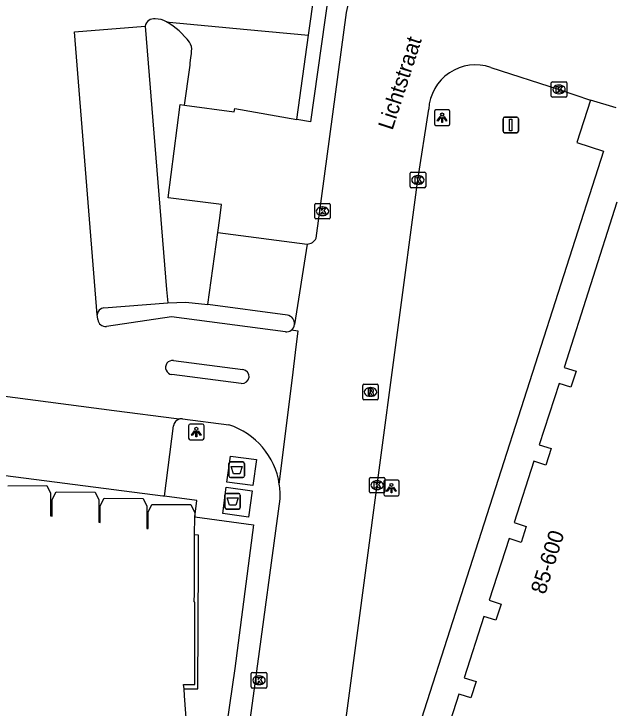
# Model space of a CAD drawing. Extents: x 160676 to 161153, y 383244 to 383713.
# Drawn here: x 160773.69 to 160812.07, y 383306.9 to 383351.55 of the extents above; entities that cross this region are included whole.
import ezdxf

# ---------------------------------------------------------------- set-up
doc = ezdxf.new("R2010")
doc.units = 0
for name, color, linetype in [('IMGEO_Afsluitpaal', 7, 'Continuous'), ('IMGEO_Afval_apart_plaats', 7, 'Continuous'), ('IMGEO_Kolk', 7, 'Continuous'), ('IMGEO_Lichtpunt', 7, 'Continuous'), ('IMGEO_Muur', 7, 'Continuous'), ('IMGEO_Openbare_ruimte_label', 7, 'Continuous'), ('IMGEO_Pand', 7, 'Continuous'), ('IMGEO_Pand_nummerreeks', 7, 'Continuous'), ('IMGEO_Parkeervlak_open', 7, 'Continuous'), ('IMGEO_Rijbaan_lokaal_open', 7, 'Continuous'), ('IMGEO_Rioolput', 7, 'Continuous'), ('IMGEO_Verkeerseiland_open', 7, 'Continuous'), ('IMGEO_Voetpad_gesloten', 7, 'Continuous'), ('IMGEO_Voetpad_open', 7, 'Continuous')]:
    doc.layers.add(name, color=color, linetype=linetype)

msp = doc.modelspace()

# ---------------------------------------------------------------- linework, layer by layer
at = {"layer": 'IMGEO_Afsluitpaal'}
for p, q in [((160805.175, 383344.01), (160805.175, 383344.81)), ((160805.175, 383344.81), (160805.175, 383344.01)), ((160805.275, 383344.91), (160806.065, 383344.91)), ((160806.065, 383344.91), (160805.275, 383344.91)), ((160806.165, 383344.81), (160806.165, 383344.01)), ((160806.165, 383344.01), (160806.165, 383344.81)), ((160806.065, 383343.91), (160805.275, 383343.91)), ((160805.275, 383343.91), (160806.065, 383343.91))]:
    msp.add_line(p, q, dxfattribs=at)
msp.add_lwpolyline([(160805.595, 383344.785), (160805.745, 383344.785), (160805.745, 383344.035), (160805.595, 383344.035), (160805.595, 383344.785)], dxfattribs=at)
for centre, start, end in [((160805.275, 383344.81), 90, 180), ((160805.275, 383344.81), 90, 180), ((160806.065, 383344.81), 0, 90), ((160806.065, 383344.81), 360, 90), ((160805.275, 383344.01), 180, 270), ((160805.275, 383344.01), 180, 270), ((160806.065, 383344.01), 270, 0), ((160806.065, 383344.01), 270, 0)]:
    msp.add_arc(centre, 0.1, start, end, dxfattribs=at)
at = {"layer": 'IMGEO_Afval_apart_plaats'}
for p, q in [((160787.535, 383321.83), (160787.535, 383322.63)), ((160787.535, 383322.63), (160787.535, 383321.83)), ((160787.635, 383322.73), (160788.425, 383322.73)), ((160788.425, 383322.73), (160787.635, 383322.73)), ((160788.525, 383322.63), (160788.525, 383321.83)), ((160788.525, 383321.83), (160788.525, 383322.63)), ((160788.425, 383321.73), (160787.635, 383321.73)), ((160787.635, 383321.73), (160788.425, 383321.73)), ((160787.275, 383319.8), (160787.275, 383320.6)), ((160787.275, 383320.6), (160787.275, 383319.8)), ((160787.375, 383320.7), (160788.165, 383320.7)), ((160788.165, 383320.7), (160787.375, 383320.7)), ((160788.265, 383320.6), (160788.265, 383319.8)), ((160788.265, 383319.8), (160788.265, 383320.6)), ((160788.165, 383319.7), (160787.375, 383319.7)), ((160787.375, 383319.7), (160788.165, 383319.7))]:
    msp.add_line(p, q, dxfattribs=at)
for points in [[(160787.678, 383322.444), (160788.382, 383322.444), (160788.233, 383321.974), (160787.827, 383321.974), (160787.678, 383322.444)], [(160787.418, 383320.414), (160788.122, 383320.414), (160787.973, 383319.944), (160787.567, 383319.944), (160787.418, 383320.414)]]:
    msp.add_lwpolyline(points, dxfattribs=at)
for centre, start, end in [((160787.635, 383322.63), 90, 180), ((160787.635, 383322.63), 90, 180), ((160788.425, 383322.63), 0, 90), ((160788.425, 383322.63), 360, 90), ((160787.635, 383321.83), 180, 270), ((160787.635, 383321.83), 180, 270), ((160788.425, 383321.83), 270, 0), ((160788.425, 383321.83), 270, 0), ((160787.375, 383320.6), 90, 180), ((160787.375, 383320.6), 90, 180), ((160788.165, 383320.6), 0, 90), ((160788.165, 383320.6), 360, 90), ((160787.375, 383319.8), 180, 270), ((160787.375, 383319.8), 180, 270), ((160788.165, 383319.8), 270, 0), ((160788.165, 383319.8), 270, 0)]:
    msp.add_arc(centre, 0.1, start, end, dxfattribs=at)
at = {"layer": 'IMGEO_Kolk'}
for p, q in [((160808.356, 383347.194), (160809.208, 383347.194)), ((160808.281, 383346.268), (160808.281, 383347.12)), ((160808.769, 383346.974), (160808.794, 383346.974)), ((160809.282, 383347.12), (160809.282, 383346.268)), ((160808.792, 383346.414), (160808.767, 383346.414)), ((160809.208, 383346.194), (160808.356, 383346.194)), ((160799.269, 383341.373), (160800.121, 383341.373)), ((160799.194, 383340.447), (160799.194, 383341.299)), ((160799.682, 383341.153), (160799.707, 383341.153)), ((160800.195, 383341.299), (160800.195, 383340.447)), ((160799.705, 383340.593), (160799.68, 383340.593)), ((160800.121, 383340.373), (160799.269, 383340.373)), ((160793.054, 383338.434), (160793.054, 383339.286)), ((160793.129, 383339.36), (160793.981, 383339.36)), ((160793.542, 383339.14), (160793.567, 383339.14)), ((160794.055, 383339.286), (160794.055, 383338.434)), ((160793.981, 383338.36), (160793.129, 383338.36)), ((160793.565, 383338.58), (160793.54, 383338.58)), ((160796.645, 383321.737), (160797.497, 383321.737)), ((160796.57, 383320.811), (160796.57, 383321.663)), ((160797.058, 383321.517), (160797.083, 383321.517)), ((160797.571, 383321.663), (160797.571, 383320.811)), ((160797.081, 383320.957), (160797.056, 383320.957)), ((160797.497, 383320.737), (160796.645, 383320.737)), ((160789.047, 383309.187), (160789.899, 383309.187)), ((160788.972, 383308.261), (160788.972, 383309.113)), ((160789.46, 383308.967), (160789.485, 383308.967)), ((160789.973, 383309.113), (160789.973, 383308.261)), ((160789.483, 383308.407), (160789.458, 383308.407)), ((160789.899, 383308.187), (160789.047, 383308.187))]:
    msp.add_line(p, q, dxfattribs=at)
for points in [[(160808.356, 383347.194), (160809.208, 383347.194)], [(160808.281, 383346.268), (160808.281, 383347.12)], [(160808.602, 383346.894), (160808.725, 383346.894), (160808.725, 383346.743), (160808.855, 383346.894), (160809.019, 383346.894), (160808.873, 383346.743), (160809.026, 383346.494), (160808.874, 383346.494), (160808.789, 383346.658), (160808.725, 383346.591), (160808.725, 383346.494), (160808.602, 383346.494), (160808.602, 383346.894)], [(160809.282, 383347.12), (160809.282, 383346.268)], [(160809.208, 383346.194), (160808.356, 383346.194)], [(160799.269, 383341.373), (160800.121, 383341.373)], [(160799.194, 383340.447), (160799.194, 383341.299)], [(160799.515, 383341.073), (160799.638, 383341.073), (160799.638, 383340.922), (160799.768, 383341.073), (160799.932, 383341.073), (160799.786, 383340.922), (160799.939, 383340.673), (160799.787, 383340.673), (160799.702, 383340.837), (160799.638, 383340.77), (160799.638, 383340.673), (160799.515, 383340.673), (160799.515, 383341.073)], [(160800.195, 383341.299), (160800.195, 383340.447)], [(160800.121, 383340.373), (160799.269, 383340.373)], [(160793.054, 383338.434), (160793.054, 383339.286)], [(160793.129, 383339.36), (160793.981, 383339.36)], [(160794.055, 383339.286), (160794.055, 383338.434)], [(160793.375, 383339.06), (160793.498, 383339.06), (160793.498, 383338.909), (160793.628, 383339.06), (160793.792, 383339.06), (160793.646, 383338.909), (160793.799, 383338.66), (160793.647, 383338.66), (160793.562, 383338.824), (160793.498, 383338.757), (160793.498, 383338.66), (160793.375, 383338.66), (160793.375, 383339.06)], [(160793.981, 383338.36), (160793.129, 383338.36)], [(160796.645, 383321.737), (160797.497, 383321.737)], [(160796.57, 383320.811), (160796.57, 383321.663)], [(160796.891, 383321.437), (160797.014, 383321.437), (160797.014, 383321.286), (160797.144, 383321.437), (160797.308, 383321.437), (160797.162, 383321.286), (160797.315, 383321.037), (160797.163, 383321.037), (160797.078, 383321.201), (160797.014, 383321.134), (160797.014, 383321.037), (160796.891, 383321.037), (160796.891, 383321.437)], [(160797.571, 383321.663), (160797.571, 383320.811)], [(160797.497, 383320.737), (160796.645, 383320.737)], [(160789.047, 383309.187), (160789.899, 383309.187)], [(160788.972, 383308.261), (160788.972, 383309.113)], [(160789.293, 383308.887), (160789.416, 383308.887), (160789.416, 383308.736), (160789.546, 383308.887), (160789.71, 383308.887), (160789.564, 383308.736), (160789.717, 383308.487), (160789.565, 383308.487), (160789.48, 383308.651), (160789.416, 383308.584), (160789.416, 383308.487), (160789.293, 383308.487), (160789.293, 383308.887)], [(160789.973, 383309.113), (160789.973, 383308.261)], [(160789.899, 383308.187), (160789.047, 383308.187)]]:
    msp.add_lwpolyline(points, dxfattribs=at)
for centre, start, end in [((160808.358, 383347.118), 91.552, 178.448), ((160808.358, 383347.118), 91.552, 178.448), ((160809.206, 383347.118), 1.552, 88.448), ((160809.206, 383347.118), 1.552, 88.448), ((160808.358, 383346.27), 181.552, 268.448), ((160808.358, 383346.27), 181.552, 268.448), ((160809.206, 383346.27), 271.552, 358.448), ((160809.206, 383346.27), 271.552, 358.448), ((160799.271, 383341.297), 91.552, 178.448), ((160799.271, 383341.297), 91.552, 178.448), ((160800.119, 383341.297), 1.552, 88.448), ((160800.119, 383341.297), 1.552, 88.448), ((160799.271, 383340.449), 181.552, 268.448), ((160799.271, 383340.449), 181.552, 268.448), ((160800.119, 383340.449), 271.552, 358.448), ((160800.119, 383340.449), 271.552, 358.448), ((160793.131, 383339.284), 91.552, 178.448), ((160793.131, 383339.284), 91.552, 178.448), ((160793.979, 383339.284), 1.552, 88.448), ((160793.979, 383339.284), 1.552, 88.448), ((160793.131, 383338.436), 181.552, 268.448), ((160793.131, 383338.436), 181.552, 268.448), ((160793.979, 383338.436), 271.552, 358.448), ((160793.979, 383338.436), 271.552, 358.448), ((160796.647, 383321.661), 91.552, 178.448), ((160796.647, 383321.661), 91.552, 178.448), ((160797.495, 383321.661), 1.552, 88.448), ((160797.495, 383321.661), 1.552, 88.448), ((160796.647, 383320.813), 181.552, 268.448), ((160796.647, 383320.813), 181.552, 268.448), ((160797.495, 383320.813), 271.552, 358.448), ((160797.495, 383320.813), 271.552, 358.448), ((160789.049, 383309.111), 91.552, 178.448), ((160789.049, 383309.111), 91.552, 178.448), ((160789.897, 383309.111), 1.552, 88.448), ((160789.897, 383309.111), 1.552, 88.448), ((160789.049, 383308.263), 181.552, 268.448), ((160789.049, 383308.263), 181.552, 268.448), ((160789.897, 383308.263), 271.552, 358.448), ((160789.897, 383308.263), 271.552, 358.448)]:
    msp.add_arc(centre, 0.0765, start, end, dxfattribs=at)
for centre, major_axis, ratio, start_param, end_param in [((160808.768, 383346.694), (-0.387, 0.002), 0.722429, 4.712389, 7.853982), ((160808.793, 383346.694), (-0.39, 0.002), 0.717154, 1.570796, 4.712389), ((160799.681, 383340.873), (-0.387, 0.002), 0.722429, 4.712389, 7.853982), ((160799.706, 383340.873), (-0.39, 0.002), 0.717154, 1.570796, 4.712389), ((160793.541, 383338.86), (-0.387, 0.002), 0.722429, 4.712389, 7.853982), ((160793.566, 383338.86), (-0.39, 0.002), 0.717154, 1.570796, 4.712389), ((160797.057, 383321.237), (-0.387, 0.002), 0.722429, 4.712389, 7.853982), ((160797.082, 383321.237), (-0.39, 0.002), 0.717154, 1.570796, 4.712389), ((160789.459, 383308.687), (-0.387, 0.002), 0.722429, 4.712389, 7.853982), ((160789.484, 383308.687), (-0.39, 0.002), 0.717154, 1.570796, 4.712389)]:
    msp.add_ellipse(centre, major_axis=major_axis, ratio=ratio, start_param=start_param, end_param=end_param, dxfattribs=at)
at = {"layer": 'IMGEO_Lichtpunt'}
for p, q in [((160801.658, 383345.378), (160800.85, 383345.378)), ((160801.658, 383345.378), (160800.85, 383345.378)), ((160800.756, 383345.283), (160800.756, 383344.476)), ((160800.756, 383345.283), (160800.756, 383344.476)), ((160801.752, 383344.476), (160801.752, 383345.283)), ((160801.752, 383344.476), (160801.752, 383345.283)), ((160800.85, 383344.382), (160801.658, 383344.382)), ((160800.85, 383344.382), (160801.658, 383344.382)), ((160784.937, 383325.063), (160784.937, 383324.256)), ((160784.937, 383325.063), (160784.937, 383324.256)), ((160785.839, 383325.158), (160785.031, 383325.158)), ((160785.839, 383325.158), (160785.031, 383325.158)), ((160785.933, 383324.256), (160785.933, 383325.063)), ((160785.933, 383324.256), (160785.933, 383325.063)), ((160785.031, 383324.162), (160785.839, 383324.162)), ((160785.031, 383324.162), (160785.839, 383324.162)), ((160797.493, 383321.456), (160797.493, 383320.649)), ((160797.493, 383321.456), (160797.493, 383320.649)), ((160798.395, 383321.551), (160797.587, 383321.551)), ((160798.395, 383321.551), (160797.587, 383321.551)), ((160798.489, 383320.649), (160798.489, 383321.456)), ((160798.489, 383320.649), (160798.489, 383321.456)), ((160797.587, 383320.555), (160798.395, 383320.555)), ((160797.587, 383320.555), (160798.395, 383320.555))]:
    msp.add_line(p, q, dxfattribs=at)
for points in [[(160801.13, 383344.947), (160801.169, 383344.919), (160800.981, 383344.657), (160800.943, 383344.684), (160801.13, 383344.947)], [(160801.342, 383344.919), (160801.38, 383344.946), (160801.567, 383344.684), (160801.528, 383344.656), (160801.342, 383344.919)], [(160801.232, 383344.899), (160801.279, 383344.899), (160801.279, 383344.577), (160801.232, 383344.577), (160801.232, 383344.899)], [(160785.311, 383324.727), (160785.35, 383324.699), (160785.162, 383324.437), (160785.124, 383324.464), (160785.311, 383324.727)], [(160785.413, 383324.679), (160785.46, 383324.679), (160785.46, 383324.357), (160785.413, 383324.357), (160785.413, 383324.679)], [(160785.523, 383324.699), (160785.561, 383324.726), (160785.748, 383324.464), (160785.709, 383324.436), (160785.523, 383324.699)], [(160797.867, 383321.12), (160797.906, 383321.092), (160797.718, 383320.83), (160797.68, 383320.857), (160797.867, 383321.12)], [(160797.969, 383321.072), (160798.016, 383321.072), (160798.016, 383320.75), (160797.969, 383320.75), (160797.969, 383321.072)], [(160798.079, 383321.092), (160798.117, 383321.119), (160798.304, 383320.857), (160798.265, 383320.829), (160798.079, 383321.092)]]:
    msp.add_lwpolyline(points, dxfattribs=at)
for centre in [(160801.255, 383345.081), (160785.436, 383324.861), (160797.992, 383321.254)]:
    msp.add_circle(centre, 0.0994, dxfattribs=at)
for centre, start, end in [((160800.85, 383345.283), 90, 180), ((160800.85, 383345.283), 90, 180), ((160801.658, 383345.283), 0, 90), ((160801.658, 383345.283), 0, 90), ((160800.85, 383344.476), 180, 270), ((160800.85, 383344.476), 180, 270), ((160801.658, 383344.476), 270, 0), ((160801.658, 383344.476), 270, 360), ((160785.031, 383325.063), 90, 180), ((160785.031, 383325.063), 90, 180), ((160785.839, 383325.063), 0, 90), ((160785.839, 383325.063), 0, 90), ((160785.031, 383324.256), 180, 270), ((160785.031, 383324.256), 180, 270), ((160785.839, 383324.256), 270, 0), ((160785.839, 383324.256), 270, 360), ((160797.587, 383321.456), 90, 180), ((160797.587, 383321.456), 90, 180), ((160798.395, 383321.456), 0, 90), ((160798.395, 383321.456), 0, 90), ((160797.587, 383320.649), 180, 270), ((160797.587, 383320.649), 180, 270), ((160798.395, 383320.649), 270, 0), ((160798.395, 383320.649), 270, 360)]:
    msp.add_arc(centre, 0.0946, start, end, dxfattribs=at)
at = {"layer": 'IMGEO_Muur'}
msp.add_lwpolyline([(160784.642, 383308.13), (160785.536, 383308.126), (160785.57, 383316.389), (160785.576, 383317.889), (160785.577, 383318.015), (160785.325, 383318.048)], dxfattribs=at)
at = {"layer": 'IMGEO_Pand'}
for points in [[(160812.507, 383339.449), (160809.099, 383328.814), (160809.87, 383328.567), (160809.547, 383327.538), (160808.776, 383327.786), (160807.505, 383323.835), (160808.276, 383323.587), (160807.93, 383322.528), (160807.159, 383322.776), (160805.888, 383318.832), (160806.658, 383318.584), (160806.332, 383317.554), (160805.562, 383317.803), (160804.281, 383313.834), (160805.052, 383313.585), (160804.718, 383312.546), (160803.946, 383312.793), (160802.682, 383308.844), (160803.453, 383308.597), (160803.105, 383307.552), (160802.409, 383307.77), (160802.332, 383307.794), (160796.79, 383290.554)], [(160773.307, 383321.203), (160775.806, 383321.216), (160776.054, 383320.717), (160776.055, 383319.264), (160776.161, 383319.25), (160776.161, 383320.31), (160776.415, 383320.808), (160778.923, 383320.79), (160779.166, 383320.286), (160779.166, 383318.856), (160779.243, 383318.846), (160779.243, 383319.899), (160779.496, 383320.398), (160782.011, 383320.385), (160782.256, 383319.881), (160782.257, 383318.451), (160782.326, 383318.441), (160782.326, 383319.498), (160782.577, 383319.997), (160785.09, 383319.987), (160785.332, 383319.46), (160785.331, 383319.191)], [(160785.325, 383318.048), (160785.331, 383319.191)], [(160784.642, 383308.13), (160784.62, 383308.419), (160785.333, 383308.411), (160785.346, 383313.718), (160785.304, 383313.73), (160785.307, 383314.278), (160785.325, 383318.048)], [(160784.931, 383304.271), (160784.675, 383307.69), (160784.642, 383308.13)]]:
    msp.add_lwpolyline(points, dxfattribs=at)
at = {"layer": 'IMGEO_Parkeervlak_open'}
for points in [[(160782.144, 383350.764), (160783.513, 383333.834), (160783.609, 383332.967)], [(160791.912, 383344.759), (160792.66, 383350.191)], [(160784.68, 383345.68), (160785.01, 383348.104), (160785.029, 383348.254), (160785.048, 383348.404), (160785.067, 383348.553), (160785.09, 383348.743), (160785.103, 383348.852), (160785.119, 383349.001), (160785.13, 383349.166)], [(160786.168, 383332.849), (160786.829, 383337.493)], [(160779.492, 383332.635), (160783.609, 383332.967)], [(160791.296, 383332.168), (160786.168, 383332.849)], [(160783.387, 383320.523), (160783.274, 383320.538), (160773.83, 383321.747), (160754.886, 383324.173)]]:
    msp.add_lwpolyline(points, dxfattribs=at)
for centre, radius, start, end in [((160780.823, 383346.537), 5.254, 37.3771, 59.0622), ((160784.326, 383349.272), 0.811, 352.4855, 34.0412), ((160779.521, 383332.174), 0.462, 93.5519, 177.7562), ((160791.212, 383331.636), 0.539, 353.5978, 81.0043)]:
    msp.add_arc(centre, radius, start, end, dxfattribs=at)
at = {"layer": 'IMGEO_Rijbaan_lokaal_open'}
for points in [[(160793.154, 383337.121), (160795.11, 383351.65), (160795.304, 383352.64), (160797.946, 383359.432)], [(160792.66, 383350.191), (160793.037, 383352.925), (160793.742, 383354.783)], [(160779.059, 383332.192), (160777.595, 383350.398), (160782.144, 383350.764)], [(160783.524, 383351.043), (160783.678, 383351.029), (160788.706, 383350.56), (160792.66, 383350.191)], [(160804.384, 383348.108), (160808.782, 383346.694), (160810.812, 383346.001)], [(160812.457, 383345.502), (160810.812, 383346.001)], [(160793.115, 383291.71), (160794.447, 383301.572), (160797.071, 383321.237), (160799.695, 383340.873), (160800.391, 383345.424)], [(160792.564, 383336.747), (160791.747, 383331.576)], [(160779.088, 383331.889), (160779.068, 383332.083), (160779.059, 383332.192)], [(160791.175, 383331.099), (160783.842, 383332.057), (160779.649, 383331.453)], [(160790.776, 383321.303), (160791.621, 383328.132), (160791.869, 383330.134), (160791.995, 383331.154), (160791.53, 383331.202)], [(160784.323, 383325.486), (160784.152, 383325.508), (160780.14, 383326.029), (160771.64, 383327.131), (160768.888, 383327.489), (160757.053, 383329.024), (160755.161, 383329.27)], [(160783.962, 383329.258), (160788.435, 383328.678)], [(160788.327, 383327.783), (160783.854, 383328.354)], [(160784.542, 383325.513), (160787.527, 383325.118)], [(160787.712, 383297.432), (160789.229, 383308.479), (160790.827, 383320.367)]]:
    msp.add_lwpolyline(points, dxfattribs=at)
for centre, radius, start, end in [((160782.705, 383350.673), 0.568, 81.4504, 170.8259), ((160782.787, 383349.723), 1.512, 60.8148, 89.9054), ((160803.398, 383345.263), 3.011, 70.8811, 176.9351), ((160792.52, 383337.469), 0.724, 273.506, 331.2351), ((160779.604, 383331.974), 0.523, 189.3186, 274.9739), ((160791.238, 383331.622), 0.512, 304.8758, 354.8784), ((160791.212, 383331.633), 0.536, 265.9927, 306.3665), ((160783.908, 383328.806), 0.455, 83.1722, 263.2023), ((160788.379, 383328.231), 0.451, 263.428, 82.8107), ((160784.496, 383324.984), 0.531, 85.0273, 109.0295), ((160786.062, 383320.579), 4.77, 8.7304, 72.1076), ((160786.15, 383320.582), 4.682, 357.3733, 8.8643)]:
    msp.add_arc(centre, radius, start, end, dxfattribs=at)
at = {"layer": 'IMGEO_Rioolput'}
for p, q in [((160796.147, 383326.806), (160796.147, 383327.658)), ((160796.222, 383327.732), (160797.074, 383327.732)), ((160796.635, 383327.512), (160796.66, 383327.512)), ((160797.148, 383327.658), (160797.148, 383326.806)), ((160797.074, 383326.732), (160796.222, 383326.732)), ((160796.658, 383326.952), (160796.633, 383326.952))]:
    msp.add_line(p, q, dxfattribs=at)
for points in [[(160796.147, 383326.806), (160796.147, 383327.658)], [(160796.222, 383327.732), (160797.074, 383327.732)], [(160797.148, 383327.658), (160797.148, 383326.806)], [(160796.736, 383327.43), (160796.484, 383327.432), (160796.484, 383327.032)], [(160796.484, 383327.032), (160796.608, 383327.032), (160796.608, 383327.194), (160796.619, 383327.194)], [(160796.662, 383327.351), (160796.608, 383327.351), (160796.608, 383327.27)], [(160796.608, 383327.27), (160796.66, 383327.27)], [(160796.666, 383327.165), (160796.737, 383327.032), (160796.877, 383327.032), (160796.812, 383327.158)], [(160797.074, 383326.732), (160796.222, 383326.732)]]:
    msp.add_lwpolyline(points, dxfattribs=at)
for centre, radius, start, end in [((160796.224, 383327.656), 0.0765, 91.552, 178.448), ((160796.224, 383327.656), 0.0765, 91.552, 178.448), ((160797.072, 383327.656), 0.0765, 1.552, 88.448), ((160797.072, 383327.656), 0.0765, 1.552, 88.448), ((160796.618, 383327.141), 0.0533, 26.0293, 88.6989), ((160796.644, 383327.459), 0.19, 274.7715, 282.9687), ((160796.668, 383327.255), 0.0964, 77.0061, 93.1865), ((160796.682, 383327.312), 0.0378, 276.6634, 79.6772), ((160796.735, 383327.32), 0.109, 350.3612, 89.416), ((160796.733, 383327.32), 0.112, 277.5842, 350.9817), ((160796.717, 383327.105), 0.108, 29.5134, 73.7905), ((160796.224, 383326.808), 0.0765, 181.552, 268.448), ((160796.224, 383326.808), 0.0765, 181.552, 268.448), ((160797.072, 383326.808), 0.0765, 271.552, 358.448), ((160797.072, 383326.808), 0.0765, 271.552, 358.448)]:
    msp.add_arc(centre, radius, start, end, dxfattribs=at)
for centre, major_axis, ratio, start_param, end_param in [((160796.634, 383327.232), (-0.387, 0.002), 0.722429, 4.712389, 7.853982), ((160796.659, 383327.232), (-0.39, 0.002), 0.717154, 1.570796, 4.712389)]:
    msp.add_ellipse(centre, major_axis=major_axis, ratio=ratio, start_param=start_param, end_param=end_param, dxfattribs=at)
at = {"layer": 'IMGEO_Verkeerseiland_open'}
msp.add_lwpolyline([(160783.609, 383332.967), (160784.768, 383333.002), (160786.168, 383332.849)], dxfattribs=at)
at = {"layer": 'IMGEO_Voetpad_gesloten'}
for points in [[(160787.401, 383321.439), (160787.627, 383323.111), (160789.306, 383322.884), (160789.08, 383321.212), (160787.401, 383321.439)], [(160787.134, 383319.411), (160787.361, 383321.103), (160789.028, 383320.879), (160788.801, 383319.188), (160787.134, 383319.411)]]:
    msp.add_lwpolyline(points, dxfattribs=at)
at = {"layer": 'IMGEO_Voetpad_open'}
for points in [[(160796.729, 383360.072), (160793.933, 383352.85), (160792.793, 383344.603), (160791.912, 383344.759)], [(160810.812, 383346.001), (160809.925, 383343.284), (160811.629, 383342.72), (160794.963, 383290.783)], [(160786.829, 383337.493), (160786.952, 383338.408), (160787.048, 383339.288), (160783.614, 383339.722), (160784.403, 383345.718), (160784.68, 383345.68)], [(160784.68, 383345.68), (160787.879, 383345.245), (160787.914, 383345.468), (160791.912, 383344.759)], [(160786.829, 383337.493), (160792.564, 383336.747)], [(160783.387, 383320.523), (160783.971, 383325.062)], [(160785.331, 383319.191), (160785.463, 383320.244), (160783.387, 383320.523)], [(160785.331, 383319.191), (160789.121, 383318.677), (160787.903, 383309.445), (160786.2, 383297.65)]]:
    msp.add_lwpolyline(points, dxfattribs=at)
msp.add_arc((160784.495, 383324.985), 0.529, 108.9209, 171.6809, dxfattribs=at)

# ---------------------------------------------------------------- texts
at = {"layer": 'IMGEO_Openbare_ruimte_label'}
msp.add_text('Lichtstraat', height=1, rotation=72.1266, dxfattribs=at).set_placement((160798.056, 383344.025))
at = {"layer": 'IMGEO_Pand_nummerreeks'}
msp.add_text('85-600', height=1, rotation=72.4391, dxfattribs=at).set_placement((160807.881, 383314.162))

doc.saveas('drawing.dxf')
